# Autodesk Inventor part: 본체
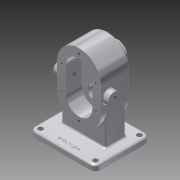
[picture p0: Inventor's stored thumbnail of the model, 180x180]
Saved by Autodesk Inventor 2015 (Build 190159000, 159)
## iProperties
Created: 2020-09
Part Number: 본체
Material: 알루미늄 6061
Document SubType Name: Modeling
Designer: Administrator
Density: 2.7 g/cm^3
Appearance: 알루미늄 - 평지
Mass: 1440.46 g
Surface Area: 785.636 cm^2
Volume: 533.505 cm^3
Author: Administrator
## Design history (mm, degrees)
sketch "스케치1"
  geometry: L1 (0, 0)-(0, 22); L2 (0, 22)-(0, -22); L3 (-40, 22)-(-40, -22); L4 (40, -22)-(40, 22); L5 (0, 22)-(0, -22); L6 (-24, 22)-(-24, -22); L7 (24, -22)-(24, 22); A1 r 40 centre (0, 22) between (40, 22) and (-40, 22); A2 r 40 centre (0, -22) between (-40, -22) and (40, -22); A3 r 24 centre (0, 22) between (24, 22) and (-24, 22); A4 r 24 centre (0, -22) between (-24, -22) and (24, -22); 2 further points
  constraints: 18 end point, 8 point on circle, 8 tangent, 4 centre point, 3 equal length, 2 midpoint, 2 vertical
  dimensions: "d0" = 22 distance of L1.start L1.end; "d1" = 44 distance of L1.end L2.end; "d2" = 80 diameter of A2; "d3" = 44 distance of L1.end L2.end (derived); "d4" = 48 diameter of A4
extrude "돌출1" new body sketch "스케치1" distance "d5" = 53; taper "d6" = 0 deg
extrude "돌출2" cut sketch "스케치1" distance "d7" = 29; taper "d8" = 0 deg
sketch "스케치2"
  geometry: C1 r 19 at (0, 22); A1 r 40 centre (0, 22) between (40, 22) and (-40, 22) reference; 1 further point
  constraints: 1 centre point, 1 coincident
  dimensions: "d10" = 38 diameter of C1
extrude "돌출3" join sketch "스케치2" distance "d11" = 17; taper "d12" = 0 deg
sketch "스케치3"
  geometry: L1 (41, 70)-(3, 70) reference; L2 (22, 70)-(22, 62.7); L3 (22, 62.7)-(36, 62.7); L4 (36, 62.7)-(36, 69.3); L5 (36, 69.3)-(22, 69.3); L6 (36, 69.3)-(36.404, 70); L7 (36, 69.3)-(37.289, 69.3); L8 (36, 69.3)-(22, 69.3); 1 further point
  constraints: 14 end point, 2 horizontal, 2 point on line, 1 collinear, 1 midpoint, 1 parallel, 1 perpendicular, 1 vertical
  dimensions: "d13" = 7.3 distance of L2.start L2.end; "d14" = 14 distance of L2.end L3.end; "d15" = 0.7 distance between parallel lines of L1 L5; "d16" = 60 deg angle of L7 L6; "d17" = 1.11648 distance from line of L7.end L6
revolve "회전1" sketch "스케치3" stored, may be unused: angle "d18" = 90 deg
sketch "스케치4"
  geometry: C1 r 12.5 at (0, 22); C2 r 8.5 at (0, 22); A1 r 24 centre (0, 22) between (24, 22) and (-24, 22) reference; 1 further point
  constraints: 2 centre point, 2 coincident
  dimensions: "d19" = 25 diameter of C1; "d20" = 17 diameter of C2
extrude "돌출4" cut sketch "스케치4" distance "d21" = 15; taper "d22" = 0 deg
extrude "돌출5" cut sketch "스케치4" distance "d23" = 46; taper "d24" = 0 deg
sketch "스케치5"
  geometry: C1 r 12.5 at (0, -22); A1 r 24 centre (0, -22) between (-24, -22) and (24, -22) reference; 1 further point
  constraints: 1 centre point, 1 coincident
  dimensions: "d25" = 25 diameter of C1
extrude "돌출6" cut sketch "스케치5" distance "d26" = 15; taper "d27" = 0 deg
sketch "스케치6"
  geometry: L1 (0, 22)-(14, 22); C1 r 11 at (14, 22)
  constraints: 2 end point, 1 centre point, 1 coincident, 1 horizontal
  dimensions: "d28" = 14 distance of L1.start L1.end; "d31" = 22 diameter of C1
extrude "돌출7" join sketch "스케치6" distance "d29" = 10; taper "d30" = 0 deg
fillet "모깎기1" dims "d32" = 3
hole "구멍1" diameter "d35" = 8.376; stored, may be unused: countersink angle "d39" = 90 deg, drill point angle "d41" = 118 deg; dims "d33" = 10, "d34" = 10, "d36" = 29, "d37" = 4, "d38" = 2, "d40" = 36.3
fillet "모깎기2" dims "d42" = 3
node "작업 평면2"
sketch "스케치7"
  geometry: L1 (19, 70)-(-19, 70) reference; L2 (0, 70)-(-60, 70); L3 (-60, 70)-(-60, -30); L4 (-60, -30)-(0, -30); L5 (0, -30)-(0, 70); L6 (0, 70)-(60, 70); L7 (60, 70)-(60, -30); L8 (60, -30)-(0, -30); L9 (0, -30)-(0, 70); 1 further point
  constraints: 16 end point, 4 parallel, 2 horizontal, 2 perpendicular, 1 midpoint
  dimensions: "d44" = 60 distance of L4.end L3.end; "d45" = 100 distance of L3.end L2.end; "d46" = 60 distance of L7.end L8.end; "d47" = 100 distance of L6.end L7.end
extrude "돌출8" join sketch "스케치7" distance "d48" = 10; taper "d49" = 0 deg
fillet "모깎기3" dims "d60" = 10
fillet "모깎기4" dims "d61" = 3
fillet "모깎기5" dims "d62" = 3
sketch "스케치9"
  geometry: L1 (-40, -53)-(40, -53) reference; L2 (-40, 0)-(40, 0) reference; L3 (-40, 0)-(-40, -53) reference; L4 (40, 0)-(40, -53) reference; L5 (-40, -26.5)-(-40, -45); L6 (-40, -26.5)-(-40, -8); L7 (-40, -8)-(40, -8); L8 (40, -8)-(40, -45); L9 (40, -45)-(-40, -45); L10 (-40, -45)-(-40, -8); 1 further point
  constraints: 12 end point, 2 parallel, 2 point on line, 1 horizontal, 1 midpoint, 1 perpendicular
  dimensions: "d63" = 18.5 distance of L5.start L5.end; "d64" = 18.5 distance of L5.start L6.end; "d65" = 80 distance of L8.end L9.end; "d66" = 37 distance of L7.end L8.end
extrude "돌출9" join sketch "스케치9" stored distance "d67" = 10; taper "d68" = 0 deg
fillet "모깎기6" dims "d69" = 3
fillet "모깎기7" dims "d70" = 3
fillet "모깎기8" dims "d71" = 3
sketch "스케치10"
  geometry: C1 r 4.5 at (-50, 20); A1 r 10 centre (-50, 20) between (-50, 30) and (-60, 20) reference; 1 further point
  constraints: 1 centre point, 1 coincident
  dimensions: "d72" = 9 diameter of C1
extrude "돌출10" cut sketch "스케치10" distance "d73" = 28; taper "d74" = 0 deg
node "작업 평면3"
sketch "스케치11"
  geometry: L1 (60, -60)-(60, 20) reference; L2 (50, 30)-(-50, 30) reference; 2 further points
  constraints: 1 other
  dimensions: "d75" = 60 distance from line of L1 point (0, 18); "d76" = 12 distance from line of L2 point (0, 18)
feature "엠보싱1" sketch "스케치11" dims "d0" = 22, "d77" = 0.5, "d78" = 0
fillet "모깎기9" dims "d79" = 0.5
sketch "스케치12"
  geometry: L1 (0, 22)-(0, 53); L2 (0, 22)-(31, 22); C1 r 12.5 at (0, -22) reference; C2 r 12.5 at (0, 22) reference; 3 further points
  constraints: 4 end point, 2 coincident, 1 horizontal, 1 vertical
  dimensions: "d80" = 31 distance of L1.start L1.end; "d81" = 31 distance of L1.start L2.end
hole "구멍3" sketch "스케치12" at (0, 53), (31, 22) diameter "d82" = 4.134; stored, may be unused: countersink angle "d86" = 90 deg, drill point angle "d88" = 118 deg; dims "d83" = 10, "d84" = 4, "d85" = 2, "d87" = 12
chamfer "모따기1" distance "d89" = 1; stored, may be unused: second distance "d90" = 2, angle "d91" = 45 deg
node "솔리드1"
mirror "대칭1"
mirror "대칭4"
mirror "대칭5"
mirror "대칭6"
mirror "대칭7"
